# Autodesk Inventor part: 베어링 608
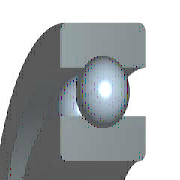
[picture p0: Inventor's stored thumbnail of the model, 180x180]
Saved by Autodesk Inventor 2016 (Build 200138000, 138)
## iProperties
IsCustomPart: 1
Created: 2012-02
Part Number: 베어링 608
Material: 강철, 연강
Description: 깊은 그루브 볼 베어링
Document SubType Name: Modeling
Standard: KS B 2023
Designer: mduedu
Standards Organization: KS
Language: ko-KR
Size Designation: 608 - 8 x 22 x 7
Categories: <MemberInstance><Categories><Category DisplayName="샤프트 부품" InternalName="7f7aeb1f-a693-4053-b835-cee3144e0d98" Mnemonic="SHFT"><Category DisplayName="베어링" Inter
Density: 1 g/cm^3
Appearance: 강철
Author: mduedu
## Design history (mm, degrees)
sketch "스케치" dims "d0" = 3.64 (= -0.26 x WD + 0.26 x BD)
  geometry: L1 (1.68, 7.5)-(5.32, 7.5); L2 (3.5, 7.5)-(3.5, 5.68); L3 (3.5, 7.5)-(3.5, 9.32); L4 (2.148, 6.282)-(0, 6.282); L5 (0, 4)-(7, 4); L6 (2.148, 8.718)-(0, 8.718); L7 (0, 11)-(7, 11); L8 (7, 4)-(7, 6.282); L9 (4.852, 6.282)-(7, 6.282); L10 (4.852, 8.718)-(7, 8.718); L11 (7, 11)-(7, 8.718); L12 (-1.4, 0)-(8.4, 0) reference; L13 (0, -0.3)-(0, 5.3) reference
  constraints: 22 end point, 4 point on line, 2 collinear, 2 perpendicular, 2 symmetric about line, 1 midpoint, 1 parallel, 14 other
  dimensions: "d9" = 8 diameter of L5 L12 (= WD); "d11" = 22 diameter of L7 L12 (= BD); "d12" = 7 distance between parallel lines of L8 L13 (= KB); "d13" = 12.564 diameter of L9 L12 (= 0.326 x BD + 0.674 x WD)
revolve "본체" stored, may be unused: angle "d6" = 90 deg
revolve "볼" stored, may be unused: angle "d7" = 90 deg
pattern_circular "IDS_ARRAYBALL[SIMPL:T]" dims angle "d3" = 360 deg
body "Solid1"
fillet "모깎기1" dims "d1" = 0.3 (= KRS)
other parameters: "WD" = 8 [user parameter; used in 5 equation terms], "BD" = 22 [user parameter; used in 5 equation terms], "KB" = 7 [user parameter; used in 1 equation term], "KRS" = 0.3 [user parameter; used in 1 equation term], "d4" = 0, "d5" = 0, "d8" = 0, "d14" = 0, "d15" = 0, "BBA" = 0 [user parameter], "BC0" = 1370000 [user parameter], "BC" = 3250000 [user parameter], "BR" = 11 (= 0.5 x BD) [user parameter], "WR" = 4 (= 0.5 x WD) [user parameter]
